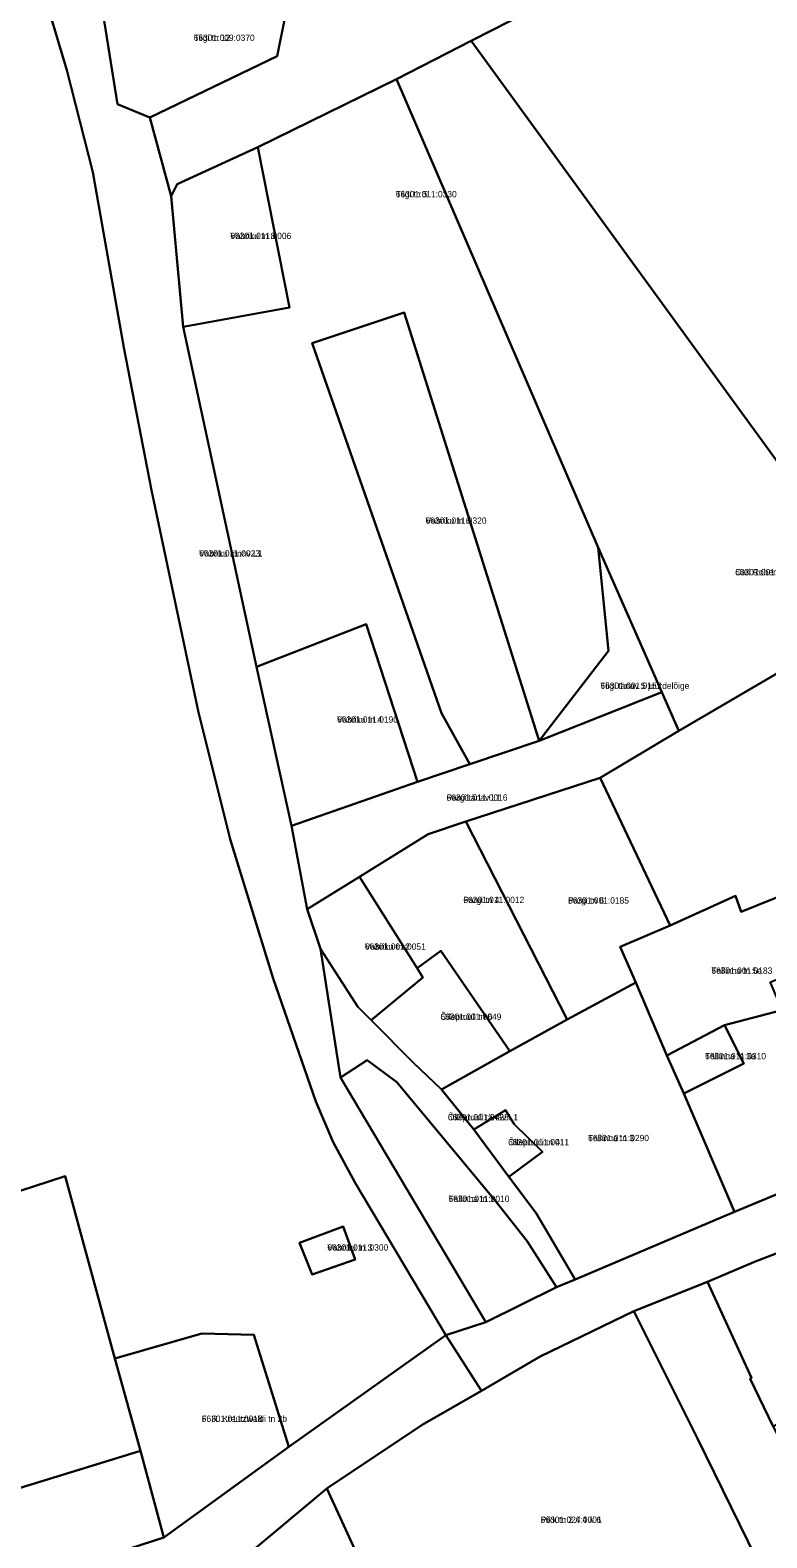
# Model space of a CAD drawing. Extents: x 632278 to 636344, y 6578401 to 6583362.
# Drawn here: x 633717.6 to 633893, y 6581440.1 to 6581799.1 of the extents above; entities that cross this region are included whole.
import ezdxf

# ---------------------------------------------------------------- set-up
doc = ezdxf.new("R2010")
doc.units = 0
for name, color, linetype in [('L_AADRESS', 7, 'Continuous'), ('PIIR', 7, 'Continuous'), ('TUNNUS', 7, 'Continuous')]:
    doc.layers.add(name, color=color, linetype=linetype)

msp = doc.modelspace()

# ---------------------------------------------------------------- linework, layer by layer
at = {"layer": 'PIIR'}
for points in [[(633746.05, 6581778.31), (633776.36, 6581792.95), (633778.15, 6581801.53), (633782.1, 6581812.81), (633788.02, 6581811.01), (633819.19, 6581824.49), (633851.9, 6581840.4), (633879.17, 6581853.47), (633905.37, 6581866.61), (633928.96, 6581878.19), (633952.86, 6581890.56), (633957.19, 6581898.78), (633964.41, 6581868.52), (633926.12, 6581849.23), (633822.63, 6581796.54), (633804.8, 6581787.45), (633771.82, 6581771.23), (633752.6, 6581762.41), (633751.15, 6581759.6)], [(633822.63, 6581796.54), (633926.12, 6581849.23), (633938.65, 6581823.98), (633951.22, 6581800.08), (633963.84, 6581775.08), (633962.93, 6581774.45), (633946.33, 6581763.28), (633949.27, 6581756.32), (633921.58, 6581741.86), (633930.19, 6581700.67), (633902.7, 6581686.51)], [(633738.36, 6581781.52), (633733.08, 6581814.8), (633778.15, 6581801.53), (633776.36, 6581792.95), (633746.05, 6581778.31)], [(633815.56, 6581636.52), (633822.29, 6581624.31), (633809.81, 6581620.16), (633797.58, 6581657.66), (633771.5, 6581647.55), (633753.99, 6581728.51), (633779.36, 6581733.05), (633771.82, 6581771.23), (633804.8, 6581787.45), (633852.87, 6581675.9), (633855.31, 6581651.37), (633838.76, 6581629.93), (633806.67, 6581731.91), (633784.74, 6581724.59)], [(633771.82, 6581771.23), (633779.36, 6581733.05), (633753.99, 6581728.51), (633751.15, 6581759.6), (633752.6, 6581762.41)], [(633822.29, 6581624.31), (633815.56, 6581636.52), (633784.74, 6581724.59), (633806.67, 6581731.91), (633838.76, 6581629.93)], [(633867.97, 6581641.48), (633838.76, 6581629.93), (633855.31, 6581651.37), (633852.87, 6581675.9)], [(633797.58, 6581657.66), (633809.81, 6581620.16), (633779.82, 6581609.69), (633771.5, 6581647.55)], [(633886.91, 6581589.22), (633885.52, 6581593), (633869.99, 6581585.97), (633853.31, 6581621.13), (633872.04, 6581632.27), (633901.12, 6581649.27), (633948.35, 6581601.84), (633933.83, 6581591.96), (633928.91, 6581588.65), (633925, 6581586.21), (633920.24, 6581583.44), (633922.88, 6581578.66), (633923.31, 6581577.15), (633908.02, 6581570.64), (633905.33, 6581577.17), (633898.43, 6581593.9)], [(633779.82, 6581609.69), (633809.81, 6581620.16), (633822.29, 6581624.31), (633838.76, 6581629.93), (633867.97, 6581641.48), (633872.04, 6581632.27), (633853.31, 6581621.13), (633821.32, 6581610.66), (633812.33, 6581607.66), (633796.01, 6581597.5), (633783.53, 6581589.83)], [(633845.45, 6581563.57), (633821.32, 6581610.66), (633853.31, 6581621.13), (633869.99, 6581585.97), (633858.05, 6581580.85), (633861.79, 6581572.33)], [(633821.32, 6581610.66), (633845.45, 6581563.57), (633831.79, 6581555.98), (633815.39, 6581579.89), (633809.71, 6581575.81), (633796.01, 6581597.5), (633812.33, 6581607.66)], [(633786.68, 6581580.42), (633783.53, 6581589.83), (633796.01, 6581597.5), (633809.71, 6581575.81), (633811.05, 6581573.59), (633798.77, 6581563.37), (633795.61, 6581566.54)], [(633861.79, 6581572.33), (633858.05, 6581580.85), (633869.99, 6581585.97), (633885.52, 6581593), (633886.91, 6581589.22), (633898.43, 6581593.9), (633905.33, 6581577.17), (633893.79, 6581572.4), (633896.56, 6581565.8), (633882.94, 6581562.22), (633869.16, 6581554.99)], [(633786.68, 6581580.42), (633795.61, 6581566.54), (633798.77, 6581563.37), (633808.82, 6581553.33), (633815.56, 6581546.88), (633823.26, 6581537.36), (633831.58, 6581526.06), (633838.05, 6581517.46), (633847.38, 6581501.65), (633842.91, 6581499.86), (633835.93, 6581510.75), (633828.24, 6581520.57), (633804.86, 6581548.61), (633797.85, 6581553.84), (633791.49, 6581549.77)], [(633811.05, 6581573.59), (633809.71, 6581575.81), (633815.39, 6581579.89), (633831.79, 6581555.98), (633815.56, 6581546.88), (633808.82, 6581553.33), (633798.77, 6581563.37)], [(633887.53, 6581553.06), (633882.94, 6581562.22), (633896.56, 6581565.8), (633908.02, 6581570.64), (633923.31, 6581577.15), (633925.83, 6581578.19), (633939.98, 6581545.06), (633942.28, 6581546.1), (633944.01, 6581542.1), (633885.29, 6581517.73), (633873.22, 6581545.96)], [(633838.05, 6581517.46), (633831.58, 6581526.06), (633839.54, 6581532.08), (633832.8, 6581538.6), (633830.74, 6581541.94), (633823.26, 6581537.36), (633815.56, 6581546.88), (633831.79, 6581555.98), (633845.45, 6581563.57), (633861.79, 6581572.33), (633869.16, 6581554.99), (633873.22, 6581545.96), (633885.29, 6581517.73), (633847.38, 6581501.65)], [(633869.16, 6581554.99), (633882.94, 6581562.22), (633887.53, 6581553.06), (633873.22, 6581545.96)], [(633797.85, 6581553.84), (633804.86, 6581548.61), (633828.24, 6581520.57), (633835.93, 6581510.75), (633842.91, 6581499.86), (633826.07, 6581491.47), (633791.49, 6581549.77)], [(633830.74, 6581541.94), (633832.8, 6581538.6), (633839.54, 6581532.08), (633831.58, 6581526.06), (633823.26, 6581537.36)], [(633654.22, 6581502.95), (633725.88, 6581526.24), (633737.73, 6581482.83), (633743.83, 6581460.83), (633688.83, 6581443.93), (633683.32, 6581460.97), (633663.75, 6581471.17), (633658.97, 6581485.85), (633656.42, 6581495.68)], [(633908.9, 6581473.01), (633908.66, 6581473.52), (633894.48, 6581466.67), (633888.99, 6581478.03), (633889.38, 6581478.21), (633878.83, 6581501.07), (633890.06, 6581505.89), (633914.43, 6581515.21), (633921.04, 6581517.31), (633933.06, 6581482.2)], [(633794.95, 6581506.44), (633784.75, 6581502.82), (633781.75, 6581510.37), (633792.15, 6581514.24)], [(633792.15, 6581514.24), (633781.75, 6581510.37), (633784.75, 6581502.82), (633794.95, 6581506.44)], [(633788.22, 6581451.87), (633810.93, 6581467.03), (633825.05, 6581475.18), (633839.02, 6581483.3), (633861.29, 6581494.14), (633876.45, 6581463.82), (633892.53, 6581431.08), (633879.79, 6581424.74), (633864.96, 6581416.48), (633851.55, 6581409.87), (633829.39, 6581398.94), (633828.13, 6581400.67), (633815.14, 6581393.29)], [(633737.73, 6581482.83), (633758.48, 6581488.79), (633770.88, 6581488.48), (633779.15, 6581461.79), (633749.45, 6581440.22), (633743.83, 6581460.83)]]:
    msp.add_lwpolyline(points, close=True, dxfattribs=at)
for points in [[(633715.84, 6581815.99), (633721.74, 6581804.98), (633726.32, 6581789.56), (633732.5, 6581765.33), (633739.89, 6581723.53), (633746.48, 6581689.57), (633757.6, 6581637.04), (633765.24, 6581606.48), (633775.45, 6581573.33), (633785.63, 6581544.01), (633789.72, 6581534.39), (633794.98, 6581524.63), (633816.52, 6581488.37), (633779.15, 6581461.79), (633770.88, 6581488.48), (633758.48, 6581488.79), (633737.73, 6581482.83), (633725.88, 6581526.24), (633654.22, 6581502.95)], [(633733.08, 6581814.8), (633738.36, 6581781.52), (633746.05, 6581778.31), (633751.15, 6581759.6), (633753.99, 6581728.51), (633771.5, 6581647.55), (633779.82, 6581609.69), (633783.53, 6581589.83), (633786.68, 6581580.42), (633791.49, 6581549.77), (633826.07, 6581491.47), (633816.52, 6581488.37), (633794.98, 6581524.63), (633789.72, 6581534.39), (633785.63, 6581544.01), (633775.45, 6581573.33), (633765.24, 6581606.48), (633757.6, 6581637.04), (633746.48, 6581689.57), (633739.89, 6581723.53), (633732.5, 6581765.33), (633726.32, 6581789.56), (633721.74, 6581804.98)], [(633901.12, 6581649.27), (633872.04, 6581632.27), (633867.97, 6581641.48), (633852.87, 6581675.9), (633804.8, 6581787.45), (633822.63, 6581796.54), (633902.7, 6581686.51)], [(633914.43, 6581515.21), (633890.06, 6581505.89), (633878.83, 6581501.07), (633861.29, 6581494.14), (633839.02, 6581483.3), (633825.05, 6581475.18), (633816.52, 6581488.37), (633826.07, 6581491.47), (633842.91, 6581499.86), (633847.38, 6581501.65), (633885.29, 6581517.73), (633944.01, 6581542.1)], [(633892.53, 6581431.08), (633876.45, 6581463.82), (633861.29, 6581494.14), (633878.83, 6581501.07), (633889.38, 6581478.21), (633888.99, 6581478.03), (633894.48, 6581466.67), (633908.64, 6581437.22)], [(633621.55, 6581398.85), (633749.45, 6581440.22), (633779.15, 6581461.79), (633816.52, 6581488.37), (633825.05, 6581475.18), (633810.93, 6581467.03), (633788.22, 6581451.87), (633763.6, 6581431.3), (633740.06, 6581421.85), (633693.69, 6581406.68)], [(633688.83, 6581443.93), (633743.83, 6581460.83), (633749.45, 6581440.22), (633621.55, 6581398.85)], [(633691.29, 6581253.68), (633686.15, 6581262.24), (633679.09, 6581282.79), (633673.1, 6581309.54), (633673.1, 6581328.8), (633675.88, 6581348.48), (633687.65, 6581378.02), (633686.65, 6581401.74), (633696.11, 6581376.23), (633749.19, 6581393.58), (633740.06, 6581421.85), (633763.6, 6581431.3), (633788.22, 6581451.87), (633815.14, 6581393.29), (633825.04, 6581371.7), (633831.17, 6581347.16), (633833.8, 6581336.59), (633859.52, 6581304.98), (633871.97, 6581276.2), (633881.18, 6581253.94)]]:
    msp.add_lwpolyline(points, dxfattribs=at)

# ---------------------------------------------------------------- texts
at = {"layer": 'L_AADRESS'}
for s, p in [('Tiigi tn 12', (633756.54, 6581796.55)), ('Tiigi tn 5', (633804.65, 6581759.31)), ('Vabriku tn 8', (633765.25, 6581749.37)), ('Vabriku tn 6', (633811.75, 6581681.59)), ('Vabriku tänav L1', (633757.82, 6581673.79)), ('Carl Robert Jakobsoni tänav T2', (633885.45, 6581669.32)), ('Tiigi tänav 5 juurdelõige', (633853.36, 6581642.28)), ('Vabriku tn 4', (633790.66, 6581634.22)), ('Pargi tänav L1', (633816.74, 6581615.65)), ('Pargi tn 4', (633820.73, 6581591.28)), ('Pargi tn 6', (633845.66, 6581591.15)), ('Vabriku tn 2', (633797.29, 6581580.16)), ('Tallinna tn 5a', (633879.8, 6581574.44)), ('Õllepruuli tn 6', (633815.28, 6581563.48)), ('Tallinna tn 3a', (633878.29, 6581554.09)), ('Õllepruuli tänav L1', (633817.03, 6581539.54)), ('Õllepruuli tn 4', (633831.4, 6581533.59)), ('Tallinna tn 3', (633850.43, 6581534.59)), ('Tallinna tn 1', (633817.2, 6581520.12)), ('Vabriku tn 3', (633788.34, 6581508.53)), ('F. R. Kreutzwaldi tn 2b', (633758.44, 6581467.76)), ('Pikk tn 2 // 4 // 6', (633839.15, 6581443.71))]:
    msp.add_text(s, height=1.5, dxfattribs=at).set_placement(p)
at = {"layer": 'TUNNUS'}
for s, p in [('66301:009:0370', (633756.54, 6581796.55)), ('66301:011:0330', (633804.65, 6581759.31)), ('66301:011:0006', (633765.25, 6581749.37)), ('66301:011:0320', (633811.75, 6581681.59)), ('66301:011:0023', (633757.82, 6581673.79)), ('66301:001:0312', (633885.45, 6581669.32)), ('66301:001:0157', (633853.36, 6581642.28)), ('66301:011:0190', (633790.66, 6581634.22)), ('66301:011:0016', (633816.74, 6581615.65)), ('66301:011:0012', (633820.73, 6581591.28)), ('66301:001:0185', (633845.66, 6581591.15)), ('66301:001:0051', (633797.29, 6581580.16)), ('66301:001:0183', (633879.8, 6581574.44)), ('66301:001:0049', (633815.28, 6581563.48)), ('66301:011:0310', (633878.29, 6581554.09)), ('66301:001:0428', (633817.03, 6581539.54)), ('66301:011:0011', (633831.4, 6581533.59)), ('66301:011:0290', (633850.43, 6581534.59)), ('66301:011:0010', (633817.2, 6581520.12)), ('66301:011:0300', (633788.34, 6581508.53)), ('66301:011:0018', (633758.44, 6581467.76)), ('66301:024:0001', (633839.15, 6581443.71))]:
    msp.add_text(s, height=1.5, dxfattribs=at).set_placement(p)

doc.saveas('drawing.dxf')
